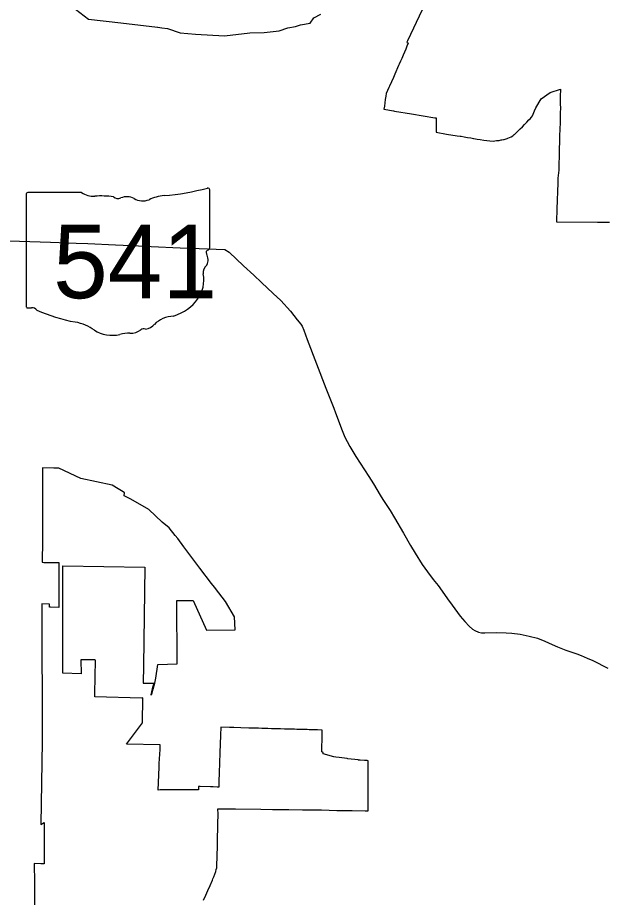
# Model space of a CAD drawing. Extents: x 1913970 to 2276415, y 78841 to 927181.
# Drawn here: x 2145735 to 2154706, y 818227 to 831652 of the extents above; entities that cross this region are included whole.
import ezdxf

# ---------------------------------------------------------------- set-up
doc = ezdxf.new("R2010")
doc.units = 0
for name, color, linetype in [('GM_X_Corporation', 7, 'Continuous'), ('GM_X_State_Route', 7, 'Continuous'), ('GM_X_State_Shield', 7, 'Continuous')]:
    doc.layers.add(name, color=color, linetype=linetype)

msp = doc.modelspace()

# ---------------------------------------------------------------- linework, layer by layer
at = {"layer": 'GM_X_Corporation'}
for points in [[(2146485, 831881), (2146819, 831629), (2147313, 831571), (2147873, 831504), (2147874, 831504), (2147939, 831498), (2148024, 831483), (2148214, 831419), (2148451, 831399), (2148892, 831375), (2149280, 831421), (2149499, 831425), (2149725, 831450), (2149862, 831493), (2149975, 831514), (2150054, 831542), (2150199, 831568), (2150254, 831650), (2150364, 831704)], [(2151910, 831771), (2151684, 831298), (2151675, 831279), (2151697, 831261), (2151678, 831214), (2151659, 831168), (2151638, 831122), (2151618, 831076), (2151598, 831028), (2151579, 830985), (2151559, 830941), (2151550, 830920), (2151492, 830788), (2151471, 830739), (2151410, 830604), (2151402, 830586), (2151382, 830539), (2151361, 830496), (2151354, 830452), (2151347, 830401), (2151340, 830353), (2151333, 830302), (2151325, 830253), (2151474, 830228), (2151489, 830225), (2151747, 830182), (2152105, 830124), (2152125, 830121), (2152124, 829901), (2152283, 829873), (2152445, 829848), (2152488, 829841), (2152504, 829840), (2152552, 829832), (2152602, 829823), (2152652, 829815), (2152695, 829809), (2152698, 829808), (2152747, 829799), (2152796, 829792), (2152850, 829781), (2152897, 829774), (2152943, 829769), (2152993, 829768), (2153018, 829769), (2153046, 829774), (2153074, 829776), (2153084, 829778), (2153099, 829780), (2153116, 829784), (2153126, 829786), (2153153, 829791), (2153163, 829794), (2153178, 829798), (2153205, 829805), (2153219, 829811), (2153245, 829821), (2153268, 829834), (2153292, 829849), (2153314, 829866), (2153318, 829868), (2153334, 829882), (2153370, 829919), (2153403, 829955), (2153439, 829987), (2153472, 830022), (2153508, 830058), (2153540, 830090), (2153557, 830109), (2153577, 830133), (2153594, 830152), (2153603, 830178), (2153613, 830205), (2153625, 830231), (2153643, 830276), (2153727, 830413), (2153862, 830508), (2154019, 830560), (2154017, 830446), (2154018, 830344), (2154019, 830262), (2154019, 830247), (2154018, 830221), (2154017, 830114), (2154016, 830028), (2154013, 829974), (2154008, 829822), (2154001, 829585), (2154001, 829582), (2153996, 829369), (2153993, 829340), (2153994, 829326), (2153982, 829202), (2153980, 829156), (2153979, 829123), (2153978, 829093), (2153976, 829030), (2153975, 829008), (2153969, 828855), (2153966, 828740), (2153959, 828536), (2153960, 828536), (2154587, 828530), (2154771, 828528)], [(2148575, 818183), (2148607, 818260), (2148639, 818333), (2148673, 818408), (2148710, 818489), (2148717, 818508), (2148728, 818538), (2148759, 818623), (2148768, 818650), (2148774, 818678), (2148774, 818706), (2148785, 819010), (2148793, 819409), (2148794, 819437), (2148794, 819497), (2148793, 819578), (2149061, 819576), (2149448, 819571), (2149627, 819570), (2149873, 819567), (2150086, 819565), (2150357, 819562), (2150371, 819562), (2150488, 819559), (2150608, 819555), (2150839, 819551), (2151039, 819547), (2151086, 819546), (2151085, 819787), (2151085, 819887), (2151084, 820312), (2151080, 820313), (2151069, 820314), (2151041, 820316), (2151030, 820317), (2150962, 820321), (2150953, 820322), (2150939, 820323), (2150934, 820324), (2150773, 820343), (2150763, 820344), (2150643, 820359), (2150593, 820368), (2150564, 820374), (2150400, 820419), (2150400, 820438), (2150381, 820447), (2150381, 820462), (2150383, 820699), (2150383, 820733), (2150384, 820781), (2150313, 820783), (2150257, 820784), (2150187, 820786), (2150155, 820787), (2150061, 820790), (2150036, 820790), (2149998, 820791), (2149959, 820793), (2149935, 820793), (2149893, 820794), (2149872, 820795), (2149822, 820796), (2149809, 820796), (2149749, 820798), (2149746, 820798), (2149740, 820798), (2149683, 820799), (2149679, 820799), (2149609, 820801), (2149554, 820803), (2149533, 820804), (2149461, 820806), (2149411, 820807), (2149397, 820808), (2149381, 820808), (2149362, 820809), (2149334, 820810), (2149266, 820811), (2149140, 820815), (2149037, 820818), (2148967, 820819), (2148836, 820823), (2148835, 820804), (2148832, 820722), (2148831, 820704), (2148821, 820432), (2148817, 820279), (2148816, 820265), (2148810, 820144), (2148808, 819984), (2148808, 819909), (2148783, 819909), (2148720, 819912), (2148678, 819913), (2148520, 819919), (2148498, 819920), (2148497, 819870), (2148492, 819869), (2148440, 819869), (2148391, 819869), (2148340, 819868), (2148290, 819868), (2148240, 819868), (2148190, 819867), (2148137, 819867), (2148122, 819867), (2148107, 819867), (2148061, 819867), (2148011, 819866), (2147961, 819866), (2147911, 819866), (2147881, 819865), (2147894, 820214), (2147896, 820272), (2147910, 820484), (2147910, 820554), (2147398, 820567), (2147641, 820891), (2147649, 821270), (2147629, 821269), (2146915, 821287), (2146916, 821337), (2146924, 821849), (2146914, 821850), (2146703, 821854), (2146704, 821639), (2146428, 821646), (2146424, 823285), (2147677, 823264), (2147659, 821765), (2147653, 821496), (2147814, 821497), (2147787, 821408), (2147770, 821320), (2147786, 821321), (2147803, 821404), (2147829, 821494), (2147847, 821570), (2147878, 821781), (2148170, 821790), (2148165, 822755), (2148413, 822759), (2148617, 822302), (2149057, 822309), (2149045, 822506), (2148908, 822743), (2148808, 822873), (2148739, 822963), (2148697, 823017), (2148516, 823252), (2148274, 823575), (2148179, 823703), (2148141, 823750), (2148049, 823864), (2147943, 823954), (2147736, 824146), (2147466, 824303), (2147363, 824354), (2147367, 824402), (2147347, 824415), (2147272, 824460), (2147179, 824516), (2146699, 824618), (2146363, 824774), (2146303, 824775), (2146292, 824775), (2146287, 824775), (2146116, 824779), (2146116, 824072), (2146117, 823671), (2146111, 823341), (2146134, 823339), (2146180, 823339), (2146226, 823338), (2146272, 823337), (2146318, 823336), (2146364, 823336), (2146364, 823287), (2146365, 823167), (2146365, 823151), (2146365, 823101), (2146365, 823051), (2146365, 823001), (2146365, 822951), (2146365, 822901), (2146365, 822851), (2146365, 822801), (2146365, 822751), (2146365, 822726), (2146366, 822651), (2146239, 822653), (2146223, 822654), (2146223, 822703), (2146104, 822705), (2146104, 822656), (2146109, 820607), (2146092, 819339), (2146142, 819371), (2146142, 819193), (2146143, 818821), (2146143, 818737), (2146090, 818739), (2145989, 818743), (2145991, 818449), (2145992, 818271), (2145993, 818059)]]:
    msp.add_lwpolyline(points, dxfattribs=at)
at = {"layer": 'GM_X_State_Route'}
for p, q in [((2145609, 828246), (2146079, 828231)), ((2146079, 828231), (2146240, 828223)), ((2146240, 828223), (2146630, 828209)), ((2146630, 828209), (2146809, 828203)), ((2146809, 828203), (2147229, 828182)), ((2147229, 828182), (2147582, 828170)), ((2147582, 828170), (2147773, 828159)), ((2147773, 828159), (2148214, 828137)), ((2148214, 828137), (2148374, 828135)), ((2148374, 828135), (2148899, 828111))]:
    msp.add_line(p, q, dxfattribs=at)
msp.add_lwpolyline([(2148899, 828111), (2148965, 828071), (2149183, 827866), (2149339, 827720), (2149456, 827612), (2149636, 827444), (2149753, 827336), (2149899, 827170), (2150002, 827040), (2150056, 826976), (2150079, 826941), (2150104, 826881), (2150154, 826740), (2150439, 825998), (2150561, 825690), (2150587, 825622), (2150689, 825351), (2150730, 825249), (2150763, 825184), (2150807, 825106), (2150899, 824953), (2151094, 824651), (2151167, 824536), (2151271, 824364), (2151312, 824296), (2151421, 824129), (2151489, 824021), (2151624, 823784), (2151732, 823595), (2151801, 823478), (2151909, 823308), (2151992, 823197), (2152079, 823079), (2152153, 822984), (2152213, 822898), (2152297, 822782), (2152367, 822686), (2152492, 822520), (2152560, 822438), (2152627, 822364), (2152680, 822322), (2152716, 822299), (2152770, 822275), (2152816, 822266), (2152867, 822263), (2153039, 822267), (2153193, 822263), (2153280, 822258), (2153405, 822242), (2153542, 822215), (2153670, 822181), (2153780, 822139), (2153896, 822084), (2153974, 822050), (2154102, 821997), (2154272, 821942), (2154334, 821918), (2154429, 821879), (2154515, 821839), (2154743, 821724)], dxfattribs=at)
at = {"layer": 'GM_X_State_Shield'}
for p, q in [((2148667, 828133), (2148667, 829023)), ((2145865, 828952), (2145865, 827250)), ((2146713, 828981), (2145893, 828981)), ((2148666, 828133), (2148667, 828133))]:
    msp.add_line(p, q, dxfattribs=at)
for centre, major_axis, start_param, end_param in [((2147669, 831300), (2971, 0), 4.814394, 5.042369), ((2148636, 829027), (31.2, 0), 6.141152, 7.989035), ((2145897, 828955), (32.5, 0), 1.712693, 3.28349), ((2146908, 829178), (315, 0), 4.042523, 4.731795), ((2147013, 828026), (1130, 0), 1.404758, 1.657858), ((2147269, 828964), (90.8, 0), 3.836095, 5.185415), ((2147403, 828767), (189, 0), 0.950623, 2.079405), ((2147647, 829037), (227, 0), 4.081561, 5.145723), ((2148048, 828461), (598, 0), 1.699011, 2.107814), ((2148660, 828068), (48.3, 0), 1.883978, 3.671073), ((2148633, 828130), (33.4, 0), 5.05454, 6.418171), ((2148352, 827955), (290, 0), 5.934695, 6.695948), ((2148778, 827761), (211, 0), 2.387724, 3.262537), ((2147835, 827648), (743, 0), 5.101752, 6.440018), ((2145897, 827247), (32.7, 0), 3.00124, 4.508301), ((2145902, 827421), (250, 0), 4.665946, 4.897461), ((2145953, 827152), (90.1, 0), 0.519207, 1.627899), ((2147091, 828681), (2146, 0), 4.195997, 4.488961), ((2146451, 826486), (671, 0), 0.823519, 1.323587), ((2148148, 826773), (407, 0), 1.647645, 2.488434), ((2147177, 827144), (426, 0), 4.026481, 4.996735), ((2147455, 827016), (227, 0), 4.691044, 5.507374), ((2147660, 826852), (63.9, 0), 1.147584, 2.315152), ((2147633, 827086), (240, 0), 4.937069, 5.64225), ((2147424, 826556), (350, 0), 1.495662, 1.94098)]:
    msp.add_ellipse(centre, major_axis=major_axis, ratio=0.8, start_param=start_param, end_param=end_param, dxfattribs=at)

# ---------------------------------------------------------------- texts
msp.add_text('541', height=1120.7, dxfattribs=at).set_placement((2146278, 827370))

doc.saveas('drawing.dxf')
